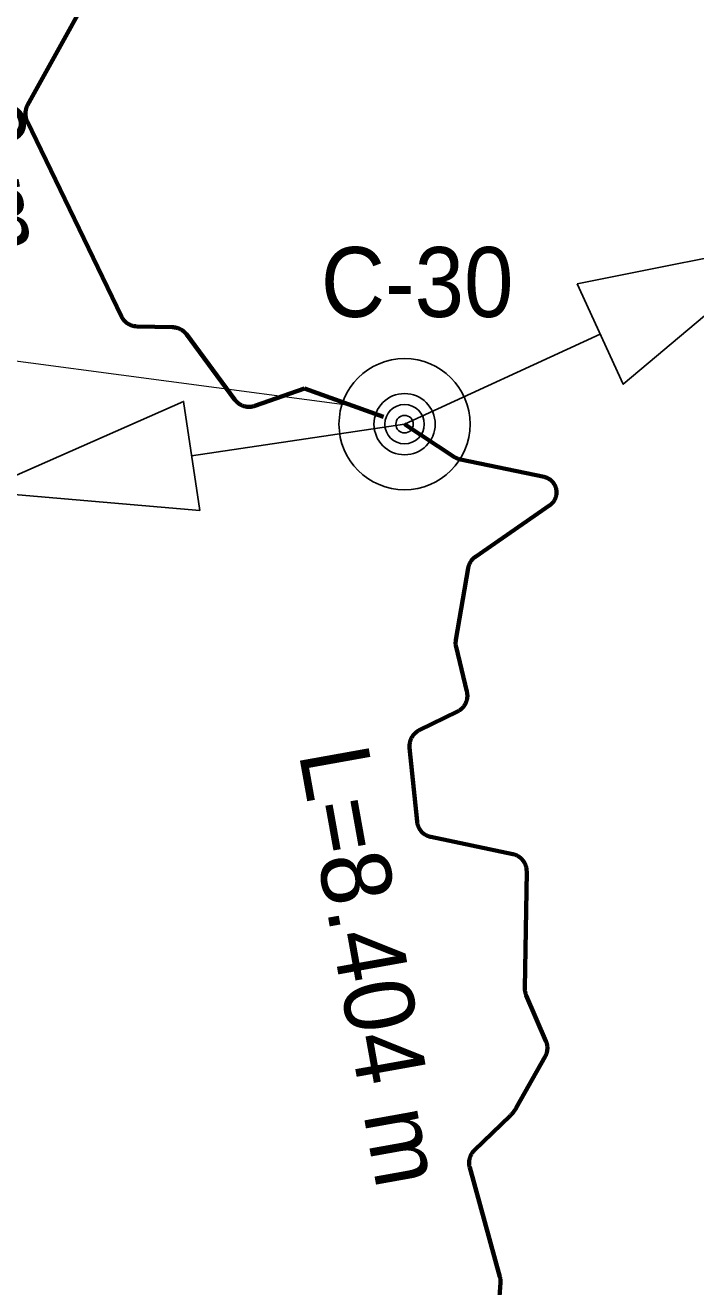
# Model space of a CAD drawing. Extents: x -1643653 to 4543381, y 1624270 to 13878484.
# Drawn here: x 741400 to 745235, y 8941082 to 8948296 of the extents above; entities that cross this region are included whole.
import ezdxf

# ---------------------------------------------------------------- set-up
doc = ezdxf.new("R2010")
doc.units = 0
doc.header["$LTSCALE"] = 160
doc.linetypes.add('MEDIUM_DASHED', pattern=[4.5, 3, -1.5])
for name, color, linetype, lineweight in [('15', 7, 'Continuous', 25), ('50', 7, 'Continuous', 13), ('54', 7, 'Continuous', 25), ('60', 7, 'Continuous', 13), ('61', 7, 'Continuous', 70)]:
    doc.layers.add(name, color=color, linetype=linetype, lineweight=lineweight)

msp = doc.modelspace()

# ---------------------------------------------------------------- linework, layer by layer
at = {"layer": '15'}
for radius in [375, 175, 112.5, 50]:
    msp.add_circle((743569.9, 8946014.8), radius, dxfattribs=at)
at = {"layer": '50'}
msp.add_lwpolyline([(743284.2, 8946117.2), (735848.9, 8947105.2), (732381.1, 8947105.2)], dxfattribs=at)
at = {"layer": '54'}
for q in [(744688.1, 8946529.7), (742352.2, 8945833.1)]:
    msp.add_line((743569.9, 8946014.8), q, dxfattribs=at)
for points in [[(744556.1, 8946816.5), (745797.1, 8947064.8), (744820.2, 8946242.8)], [(742398.8, 8945520.8), (741137.9, 8945629.4), (742305.7, 8946145.4)]]:
    msp.add_lwpolyline(points, close=True, dxfattribs=at)
at = {"layer": '60', "lineweight": 25}
msp.add_spline([(814781, 9009175.5), (814787.2, 9009173.4), (814796.9, 9009173.4), (814799.4, 9009172.4), (814805.1, 9009174.5), (814805.6, 9009176.5), (814811.7, 9009179.5), (814811.7, 9009179.5), (814801.5, 9009181), (814790.7, 9009181.5), (814784.1, 9009183.1), (814777.4, 9009185.1), (814778.4, 9009175.5)], degree=3, dxfattribs=at)
at = {"layer": '61', "linetype": 'MEDIUM_DASHED'}
msp.add_line((742998.5, 8946219.6), (743569.9, 8946014.8), dxfattribs=at)
at = {"layer": '61'}
for points in [[(742258.7, 8946567.7), (742255.9, 8946568.1), (742253.1, 8946568.4), (742250.2, 8946568.7), (742247.4, 8946568.9), (742244.6, 8946569), (742244.4, 8946569.1), (742038.3, 8946574.3), (742035.5, 8946574.4), (742032.6, 8946574.6), (742029.8, 8946574.8), (742027, 8946575.2), (742024.2, 8946575.6), (742021.4, 8946576.1), (742018.7, 8946576.7), (742015.9, 8946577.4), (742013.2, 8946578.1), (742010.5, 8946578.9), (742007.8, 8946579.8), (742005.1, 8946580.8), (742002.5, 8946581.9), (741999.9, 8946583), (741997.3, 8946584.2), (741994.8, 8946585.4), (741992.3, 8946586.8), (741989.9, 8946588.2), (741987.5, 8946589.7), (741985.1, 8946591.2), (741982.8, 8946592.8), (741980.5, 8946594.5), (741978.2, 8946596.2), (741976.1, 8946598), (741973.9, 8946599.9), (741971.9, 8946601.8), (741969.8, 8946603.8), (741967.9, 8946605.8), (741966, 8946607.9), (741964.1, 8946610.1), (741962.3, 8946612.2), (741960.6, 8946614.5), (741959, 8946616.8), (741957.4, 8946619.1), (741955.8, 8946621.5), (741954.4, 8946623.9), (741953, 8946626.4), (741951.7, 8946628.9), (741950.8, 8946630.8), (741411.5, 8947747.1), (741410.3, 8947749.7), (741409.2, 8947752.3), (741408.2, 8947754.9), (741407.2, 8947757.5), (741406.3, 8947760.2), (741405.5, 8947762.9), (741404.7, 8947765.7), (741404.1, 8947768.4), (741403.5, 8947771.2), (741403, 8947774), (741402.5, 8947776.8), (741402.2, 8947779.6), (741401.9, 8947782.4), (741401.7, 8947785.2), (741401.6, 8947788), (741401.6, 8947790.8), (741401.6, 8947793.7), (741401.8, 8947796.5), (741402, 8947799.3), (741402.2, 8947802.1), (741402.6, 8947804.9), (741403.1, 8947807.7), (741403.6, 8947810.5), (741404.2, 8947813.3), (741404.9, 8947816), (741405.6, 8947818.8), (741406.5, 8947821.4), (741407.4, 8947824.1), (741408.3, 8947826.8), (741409.4, 8947829.4), (741410.5, 8947832), (741411.8, 8947834.6), (741413, 8947837.1), (741414.1, 8947839.1), (741930.3, 8948771.1)], [(742998.5, 8946219.6), (742713.4, 8946119.4), (742710.7, 8946118.5), (742708, 8946117.7), (742705.3, 8946117), (742702.5, 8946116.3), (742699.8, 8946115.7), (742697, 8946115.2), (742694.2, 8946114.8), (742691.4, 8946114.4), (742688.6, 8946114.1), (742685.7, 8946113.9), (742682.9, 8946113.8), (742680.1, 8946113.8), (742677.2, 8946113.8), (742674.4, 8946114), (742671.6, 8946114.2), (742668.8, 8946114.4), (742666, 8946114.8), (742663.2, 8946115.3), (742660.4, 8946115.8), (742657.7, 8946116.4), (742654.9, 8946117.1), (742652.2, 8946117.8), (742649.5, 8946118.6), (742646.8, 8946119.6), (742644.2, 8946120.5), (742641.5, 8946121.6), (742638.9, 8946122.7), (742636.4, 8946123.9), (742633.8, 8946125.2), (742631.4, 8946126.6), (742628.9, 8946128), (742626.5, 8946129.5), (742624.1, 8946131), (742621.8, 8946132.6), (742619.6, 8946134.3), (742617.3, 8946136.1), (742615.2, 8946137.9), (742613, 8946139.7), (742611, 8946141.7), (742609, 8946143.7), (742607, 8946145.7), (742605.1, 8946147.8), (742603.3, 8946150), (742601.5, 8946152.2), (742599.9, 8946154.2), (742322.2, 8946528.7), (742320.5, 8946530.9), (742318.7, 8946533.1), (742316.8, 8946535.2), (742314.9, 8946537.3), (742313, 8946539.4), (742311, 8946541.4), (742308.9, 8946543.3), (742306.8, 8946545.2), (742304.6, 8946547), (742302.4, 8946548.7), (742300.1, 8946550.4), (742297.8, 8946552), (742295.4, 8946553.6), (742293, 8946555), (742290.5, 8946556.4), (742288, 8946557.8), (742285.5, 8946559.1), (742283, 8946560.2), (742280.4, 8946561.4), (742277.7, 8946562.4), (742275.1, 8946563.4), (742272.4, 8946564.3), (742269.7, 8946565.1), (742267, 8946565.9), (742264.2, 8946566.6), (742261.5, 8946567.1), (742258.7, 8946567.7)], [(743569.2, 8946014.6), (743856.2, 8945827), (743858.6, 8945825.4), (743861, 8945824), (743863.5, 8945822.6), (743866, 8945821.3), (743868.6, 8945820.1), (743871.1, 8945818.9), (743873.8, 8945817.8), (743876.4, 8945816.8), (743879.1, 8945815.9), (743881.8, 8945815), (743884.5, 8945814.2), (743887.2, 8945813.5), (743890, 8945812.9), (743890.5, 8945812.8), (744367.5, 8945712.9), (744370.1, 8945712.3), (744372.7, 8945711.7), (744375.3, 8945710.9), (744377.9, 8945710.1), (744380.4, 8945709.2), (744382.9, 8945708.2), (744385.4, 8945707.2), (744387.8, 8945706.1), (744390.2, 8945704.9), (744392.6, 8945703.6), (744394.9, 8945702.3), (744397.2, 8945700.9), (744399.5, 8945699.4), (744401.7, 8945697.9), (744403.8, 8945696.3), (744405.9, 8945694.6), (744408, 8945692.9), (744410, 8945691.1), (744411.9, 8945689.3), (744413.8, 8945687.4), (744415.6, 8945685.4), (744417.4, 8945683.4), (744419.1, 8945681.3), (744420.8, 8945679.2), (744422.4, 8945677.1), (744423.9, 8945674.9), (744425.4, 8945672.6), (744426.8, 8945670.3), (744428.1, 8945668), (744429.3, 8945665.6), (744430.5, 8945663.2), (744431.6, 8945660.8), (744432.6, 8945658.3), (744433.6, 8945655.8), (744434.5, 8945653.2), (744435.3, 8945650.7), (744436, 8945648.1), (744436.7, 8945645.5), (744437.3, 8945642.9), (744437.8, 8945640.2), (744438.2, 8945637.6), (744438.5, 8945634.9)], [(743941.3, 8945215.8), (743942.5, 8945218.4), (743943.8, 8945220.9), (743945.1, 8945223.4), (743946.5, 8945225.9), (743948, 8945228.3), (743949.6, 8945230.6), (743951.2, 8945233), (743952.8, 8945235.2), (743954.6, 8945237.5), (743956.4, 8945239.6), (743958.3, 8945241.8), (743960.2, 8945243.8), (743962.2, 8945245.8), (743964.2, 8945247.8), (743966.3, 8945249.7), (743968.5, 8945251.5), (743970.7, 8945253.3), (743972.9, 8945255), (743975.2, 8945256.7), (743975.5, 8945256.8), (744400.3, 8945550.8), (744402.5, 8945552.4), (744404.6, 8945554), (744406.7, 8945555.7), (744408.7, 8945557.5), (744410.7, 8945559.3), (744412.7, 8945561.1), (744414.5, 8945563.1), (744416.3, 8945565), (744418.1, 8945567.1), (744419.8, 8945569.2), (744421.4, 8945571.3), (744423, 8945573.5), (744424.5, 8945575.7), (744425.9, 8945578), (744427.3, 8945580.3), (744428.6, 8945582.6), (744429.8, 8945585), (744430.9, 8945587.4), (744432, 8945589.9), (744433, 8945592.4), (744434, 8945594.9), (744434.8, 8945597.4), (744435.6, 8945600), (744436.3, 8945602.6), (744436.9, 8945605.2), (744437.5, 8945607.8), (744437.9, 8945610.5), (744438.3, 8945613.1), (744438.6, 8945615.8), (744438.9, 8945618.5), (744439, 8945621.1), (744439.1, 8945623.8), (744439.1, 8945626.5), (744439, 8945629.2), (744438.8, 8945631.9), (744438.6, 8945634.5), (744438.2, 8945637.2), (744437.8, 8945639.9), (744437.3, 8945642.5), (744436.8, 8945645.1), (744436.1, 8945647.7), (744435.4, 8945650.3), (744434.6, 8945652.9), (744433.7, 8945655.4), (744432.8, 8945657.9), (744431.8, 8945660.4), (744430.7, 8945662.8), (744429.5, 8945665.3), (744428.3, 8945667.6), (744427, 8945670), (744425.6, 8945672.3), (744424.1, 8945674.5), (744422.6, 8945676.8), (744421, 8945678.9), (744419.4, 8945681), (744417.7, 8945683.1), (744415.9, 8945685.1), (744414.1, 8945687.1), (744412.2, 8945689), (744410.3, 8945690.9), (744408.3, 8945692.7), (744406.2, 8945694.4), (744404.1, 8945696.1), (744402, 8945697.7), (744399.8, 8945699.2), (744397.5, 8945700.7), (744395.2, 8945702.1), (744392.9, 8945703.4), (744390.6, 8945704.7), (744388.2, 8945705.9), (744385.7, 8945707.1), (744383.3, 8945708.1), (744380.8, 8945709.1), (744378.2, 8945710), (744375.7, 8945710.8), (744373.1, 8945711.6), (744370.5, 8945712.3), (744367.9, 8945712.9), (744367.5, 8945712.9)], [(743606.7, 8944214.2), (743607.9, 8944216.8), (743609.1, 8944219.3), (743610.4, 8944221.8), (743611.8, 8944224.3), (743613.2, 8944226.7), (743614.8, 8944229.1), (743616.3, 8944231.4), (743618, 8944233.7), (743619.7, 8944236), (743621.5, 8944238.2), (743623.3, 8944240.3), (743625.2, 8944242.4), (743627.2, 8944244.5), (743629.2, 8944246.5), (743631.2, 8944248.4), (743633.3, 8944250.3), (743635.5, 8944252.1), (743637.7, 8944253.8), (743640, 8944255.5), (743642.3, 8944257.2), (743644.7, 8944258.7), (743647.1, 8944260.2), (743649.5, 8944261.6), (743652, 8944263), (743654.2, 8944264.1), (743873.4, 8944372.5), (743875.9, 8944373.8), (743878.4, 8944375.1), (743880.8, 8944376.6), (743883.2, 8944378.1), (743885.6, 8944379.6), (743887.9, 8944381.3), (743890.2, 8944383), (743892.4, 8944384.7), (743894.6, 8944386.5), (743896.7, 8944388.4), (743898.7, 8944390.4), (743900.7, 8944392.4), (743902.7, 8944394.4), (743904.6, 8944396.5), (743906.4, 8944398.7), (743908.1, 8944400.9), (743909.8, 8944403.2), (743911.5, 8944405.5), (743913.1, 8944407.8), (743914.6, 8944410.2), (743916, 8944412.7), (743917.3, 8944415.1), (743918.6, 8944417.7), (743919.9, 8944420.2), (743921, 8944422.8), (743922.1, 8944425.4), (743923.1, 8944428), (743924, 8944430.7), (743924.9, 8944433.4), (743925.6, 8944436.1), (743926.3, 8944438.9), (743927, 8944441.6), (743927.5, 8944444.4), (743928, 8944447.2), (743928.3, 8944450), (743928.6, 8944452.8), (743928.9, 8944455.6), (743929, 8944458.5), (743929.1, 8944461.3), (743929.1, 8944464.1), (743929, 8944466.9), (743928.8, 8944469.8), (743928.5, 8944472.6), (743928.2, 8944475.4), (743927.8, 8944478.2), (743927.3, 8944481), (743926.7, 8944483.7), (743926.3, 8944485.6), (743864.7, 8944741.1), (743864, 8944743.8), (743863.5, 8944746.6), (743863, 8944749.4), (743862.6, 8944752.2), (743862.3, 8944755), (743862.1, 8944757.8), (743862, 8944760.6), (743861.9, 8944763.5), (743861.9, 8944766.3), (743862, 8944769.1), (743862.2, 8944771.9), (743862.4, 8944774.8), (743862.7, 8944777.6), (743863.1, 8944780.4), (743863.3, 8944781.4), (743933.8, 8945191.6), (743934.4, 8945194.3), (743935, 8945197.1), (743935.6, 8945199.9), (743936.4, 8945202.6), (743937.2, 8945205.3), (743938.1, 8945208), (743939.1, 8945210.6), (743940.2, 8945213.2), (743941.3, 8945215.8)], [(744261.2, 8943495.3), (744260.1, 8943497.9), (744258.9, 8943500.5), (744257.7, 8943503), (744256.4, 8943505.5), (744255, 8943508), (744253.6, 8943510.4), (744252.1, 8943512.8), (744250.5, 8943515.2), (744248.8, 8943517.4), (744247.1, 8943519.7), (744245.3, 8943521.9), (744243.5, 8943524.1), (744241.6, 8943526.2), (744239.7, 8943528.2), (744237.7, 8943530.2), (744235.6, 8943532.1), (744233.5, 8943534), (744231.3, 8943535.8), (744229.1, 8943537.6), (744226.8, 8943539.3), (744224.5, 8943540.9), (744222.1, 8943542.4), (744219.7, 8943543.9), (744217.3, 8943545.3), (744214.8, 8943546.7), (744212.3, 8943548), (744209.7, 8943549.2), (744207.1, 8943550.3), (744204.5, 8943551.4), (744201.8, 8943552.4), (744199.2, 8943553.3), (744196.5, 8943554.1), (744193.8, 8943554.9), (744191, 8943555.6), (744188.8, 8943556), (743720.5, 8943654), (743717.8, 8943654.7), (743715, 8943655.3), (743712.3, 8943656.1), (743709.6, 8943657), (743706.9, 8943657.9), (743704.3, 8943658.9), (743701.7, 8943660), (743699.1, 8943661.1), (743696.5, 8943662.3), (743694, 8943663.6), (743691.6, 8943665), (743689.1, 8943666.4), (743686.7, 8943667.9), (743684.4, 8943669.5), (743682.1, 8943671.1), (743679.8, 8943672.8), (743677.6, 8943674.6), (743675.4, 8943676.4), (743673.3, 8943678.3), (743671.3, 8943680.3), (743669.3, 8943682.3), (743667.3, 8943684.3), (743665.4, 8943686.4), (743663.6, 8943688.6), (743661.8, 8943690.8), (743660.2, 8943693.1), (743658.5, 8943695.4), (743657, 8943697.7), (743655.5, 8943700.1), (743654, 8943702.6), (743652.7, 8943705.1), (743651.4, 8943707.6), (743650.2, 8943710.1), (743649, 8943712.7), (743647.9, 8943715.3), (743647, 8943718), (743646, 8943720.7), (743645.2, 8943723.3), (743644.4, 8943726.1), (743643.7, 8943728.8), (743643.1, 8943731.6), (743642.6, 8943734.3), (743642.1, 8943737.1), (743641.7, 8943739.9), (743641.5, 8943741.9), (743599, 8944164.4), (743598.7, 8944167.2), (743598.6, 8944170), (743598.5, 8944172.9), (743598.5, 8944175.7), (743598.6, 8944178.5), (743598.7, 8944181.3), (743599, 8944184.2), (743599.3, 8944187), (743599.7, 8944189.8), (743600.2, 8944192.6), (743600.7, 8944195.3), (743601.3, 8944198.1), (743602, 8944200.8), (743602.8, 8944203.6), (743603.7, 8944206.2), (743604.6, 8944208.9), (743605.6, 8944211.6), (743606.7, 8944214.2)], [(743942.6, 8941816.8), (743943.4, 8941819.5), (743944.3, 8941822.2), (743945.2, 8941824.8), (743946.2, 8941827.5), (743947.3, 8941830.1), (743948.5, 8941832.7), (743949.7, 8941835.2), (743951, 8941837.7), (743952.4, 8941840.2), (743953.8, 8941842.6), (743955.3, 8941845), (743956.9, 8941847.3), (743958.6, 8941849.6), (743960.3, 8941851.9), (743962.1, 8941854.1), (743963.9, 8941856.2), (743965.8, 8941858.3), (743967.8, 8941860.4), (743969.5, 8941862.1), (744173.7, 8942059.7), (744176.6, 8942062.6), (744179.4, 8942065.4), (744182.1, 8942068.3), (744184.8, 8942071.3), (744187.4, 8942074.3), (744189.9, 8942077.4), (744192.4, 8942080.6), (744194.8, 8942083.7), (744197.2, 8942087), (744199.5, 8942090.2), (744201.7, 8942093.6), (744203.9, 8942096.9), (744206, 8942100.3), (744208, 8942103.8), (744208.9, 8942105.3), (744373.8, 8942398.2), (744375.2, 8942400.7), (744376.4, 8942403.2), (744377.7, 8942405.8), (744378.8, 8942408.3), (744379.8, 8942411), (744380.8, 8942413.6), (744381.8, 8942416.3), (744382.6, 8942419), (744383.3, 8942421.7), (744384, 8942424.5), (744384.6, 8942427.2), (744385.2, 8942430), (744385.6, 8942432.8), (744386, 8942435.6), (744386.3, 8942438.4), (744386.5, 8942441.2), (744386.6, 8942444.1), (744386.7, 8942446.9), (744386.6, 8942449.7), (744386.5, 8942452.5), (744386.3, 8942455.4), (744386.1, 8942458.2), (744385.7, 8942461), (744385.3, 8942463.8), (744384.8, 8942466.6), (744384.2, 8942469.3), (744383.5, 8942472.1), (744382.8, 8942474.8), (744382, 8942477.5), (744381.1, 8942480.2), (744380.1, 8942482.8), (744379.1, 8942485.5), (744378.5, 8942486.8), (744265.9, 8942748.1), (744264.8, 8942750.7), (744263.8, 8942753.3), (744262.9, 8942756), (744262.1, 8942758.7), (744261.3, 8942761.4), (744260.6, 8942764.1), (744259.9, 8942766.9), (744259.4, 8942769.7), (744258.9, 8942772.5), (744258.5, 8942775.3), (744258.2, 8942778.1), (744258, 8942780.9), (744257.8, 8942783.7), (744257.8, 8942786.5), (744257.8, 8942789.2), (744268.3, 8943456.6), (744268.3, 8943459.4), (744268.2, 8943462.2), (744268.1, 8943465.1), (744267.8, 8943467.9), (744267.5, 8943470.7), (744267.1, 8943473.5), (744266.7, 8943476.3), (744266.1, 8943479.1), (744265.5, 8943481.8), (744264.8, 8943484.6), (744264, 8943487.3), (744263.1, 8943490), (744262.2, 8943492.6), (744261.2, 8943495.3)], [(744090.6, 8940694), (744118.5, 8941105.6), (744118.6, 8941108.4), (744118.7, 8941111.3), (744118.7, 8941114.1), (744118.6, 8941116.9), (744118.4, 8941119.7), (744118.2, 8941122.6), (744117.8, 8941125.4), (744117.5, 8941128.2), (744117, 8941130.9), (744116.4, 8941133.7), (744115.8, 8941136.5), (744115.1, 8941139), (743942.7, 8941763.7), (743941.9, 8941766.4), (743941.3, 8941769.1), (743940.7, 8941771.9), (743940.3, 8941774.7), (743939.9, 8941777.5), (743939.5, 8941780.3), (743939.3, 8941783.1), (743939.1, 8941786), (743939.1, 8941788.8), (743939.1, 8941791.6), (743939.1, 8941794.4), (743939.3, 8941797.3), (743939.5, 8941800.1), (743939.8, 8941802.9), (743940.2, 8941805.7), (743940.7, 8941808.5), (743941.3, 8941811.2), (743941.9, 8941814), (743942.6, 8941816.8)]]:
    msp.add_lwpolyline(points, dxfattribs=at)

# ---------------------------------------------------------------- texts
at = {"layer": '15', "width": 0.95}
msp.add_text('C-30', height=400, dxfattribs=at).set_placement((743091.2, 8946627.8))
at = {"layer": '50'}
for s, p in [('L=8.396 m', (740683.5, 8949462.7)), ('L=8.404 m', (742963.8, 8944133.9))]:
    msp.add_text(s, height=400, rotation=280.171, dxfattribs=at).set_placement(p)

doc.saveas('drawing.dxf')
